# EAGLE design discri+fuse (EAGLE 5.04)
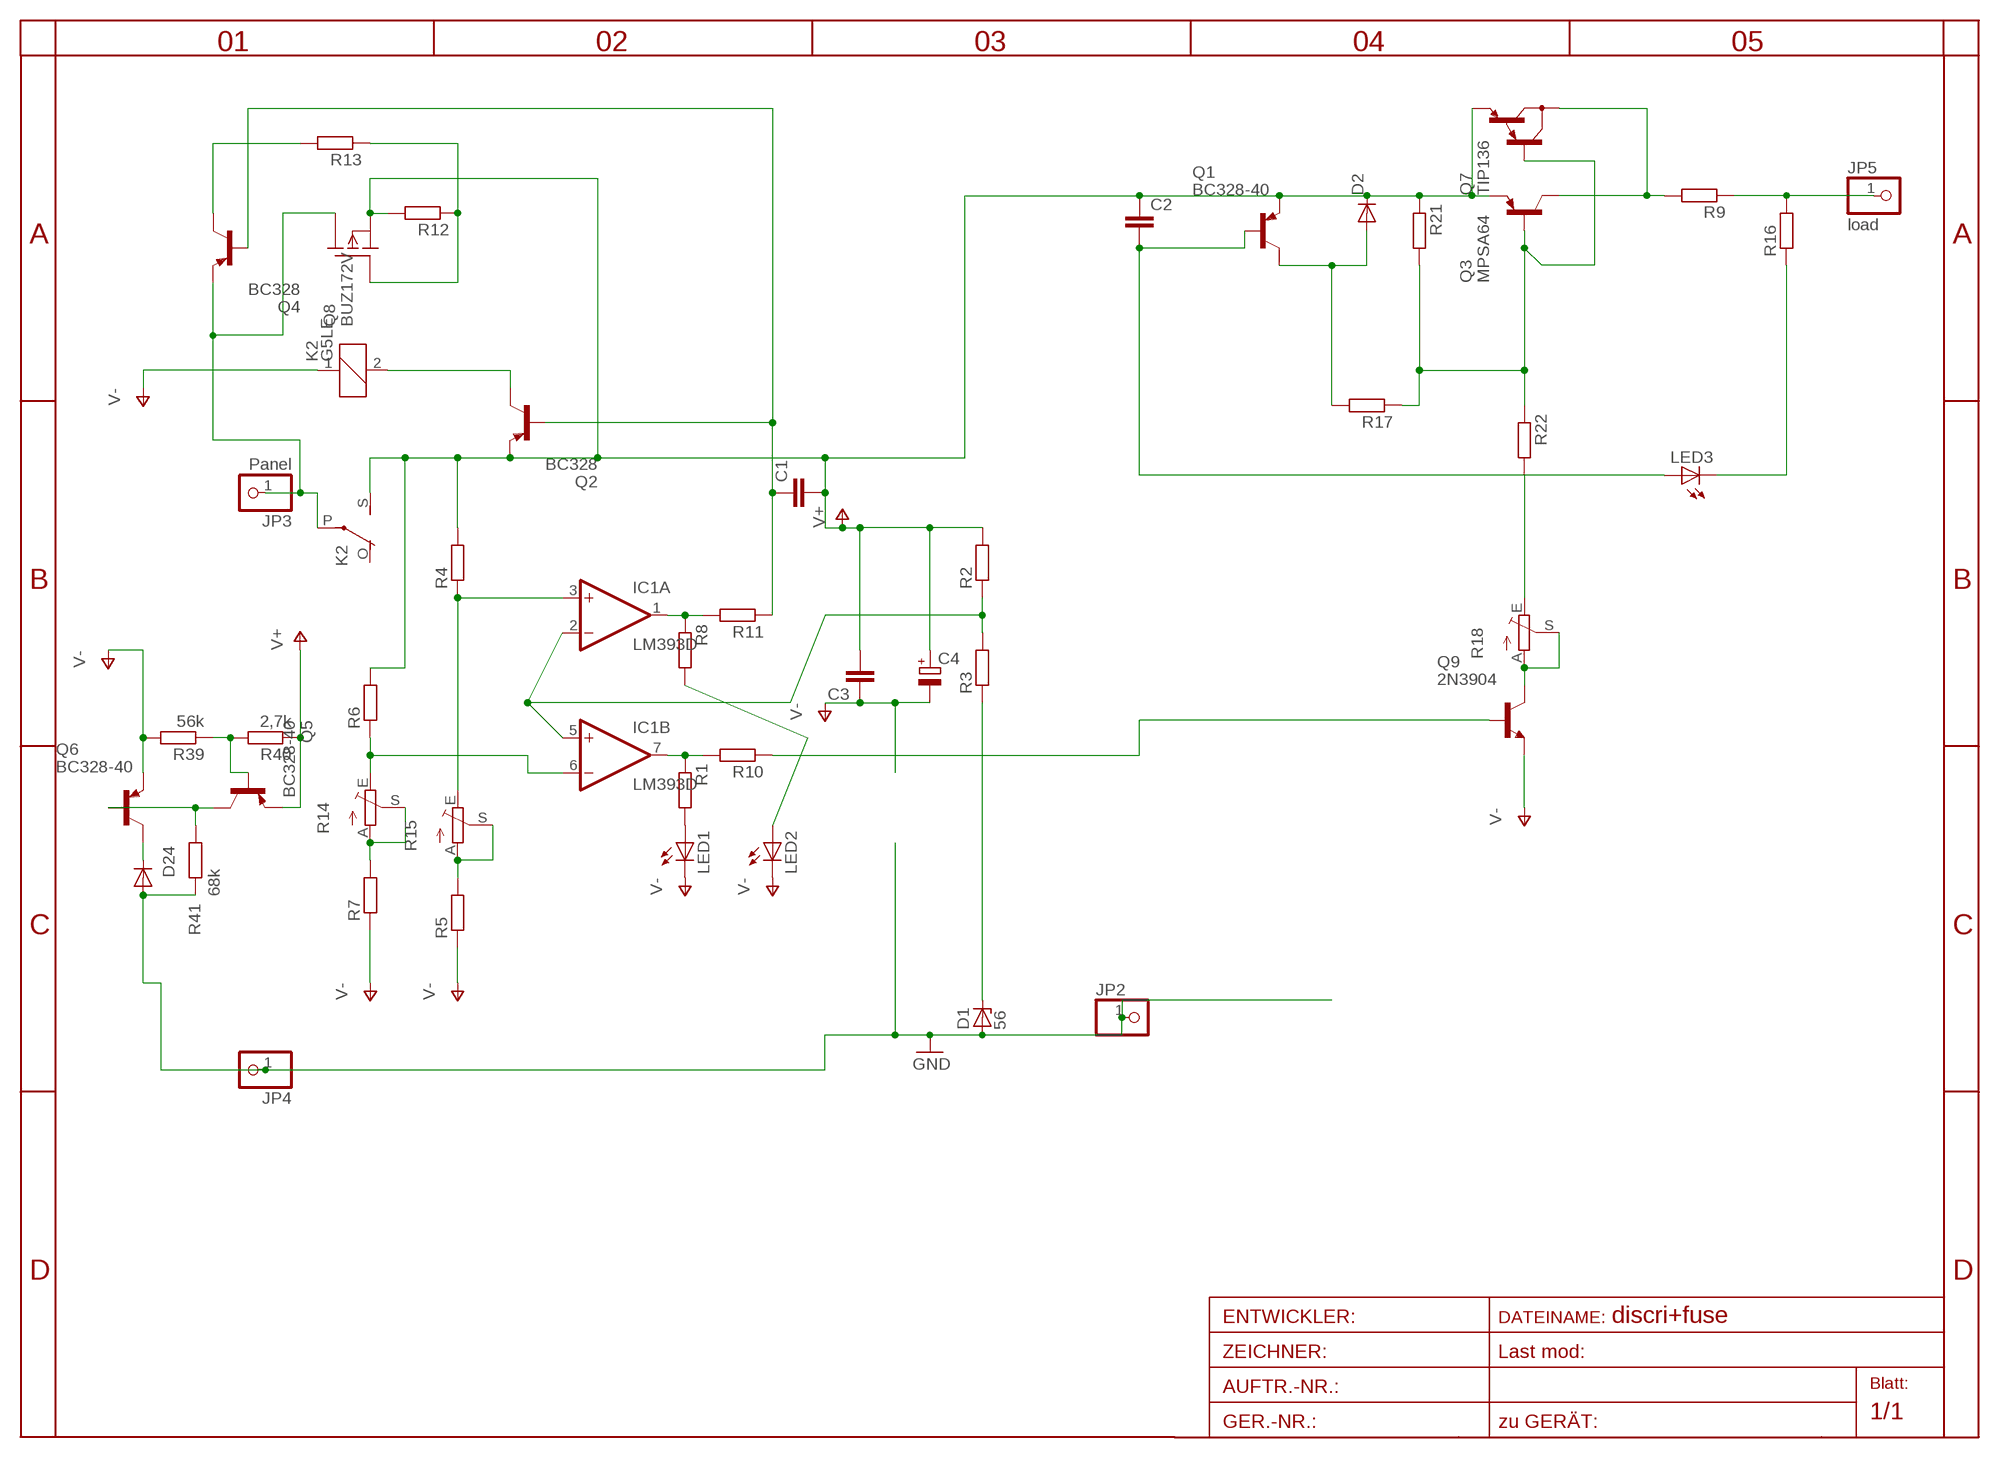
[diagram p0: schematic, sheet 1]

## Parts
C1  C-EU025-025X050  [C025-025X050]
C2  C-EU025-024X044  [C025-024X044]
C3  C-EU025-025X050  [C025-025X050]
C4  CPOL-EU5-13  [2,5-5-FLAT]
D1  56  ZENER-DIODEDO35Z10  [DO35Z10]
D2  DIODE-D-5  [D-5]
D24  Z20  DIODE-D-7.5  [D-7.5]
IC1  LM393D  [SO08]
JP2  PINHD-1X1  [1X01]
JP3  Panel  PINHD-1X1  [1X01]
JP4  PINHD-1X1  [1X01]
JP5  load  PINHD-1X1  [1X01]
K2  G5LE  [G5LE]
LED1  LED3MM  [LED3MM]
LED2  LED3MM  [LED3MM]
LED3  LED3MM  [LED3MM]
Q1  BC328-40  [TO92-EBC]
Q2  BC328  [TO92-EBC]
Q3  MPSA64  [TO92-CBE]
Q4  BC328  [TO92-EBC]
Q5  BC328-40  [TO92-EBC]
Q6  BC328-40  [TO92-EBC]
Q7  TIP136  [TO220]
Q8  BUZ172V  [TO220V]
Q9  2N3904  [TO92]
R1  R-EU_0207/15  [0207/15]
R2  R-EU_0204/7  [0204/7]
R3  R-EU_0204/7  [0204/7]
R4  R-EU_0204/7  [0204/7]
R5  R-EU_0204/7  [0204/7]
R6  R-EU_0204/7  [0204/7]
R7  R-EU_0204/7  [0204/7]
R8  R-EU_0207/20  [0207/20]
R9  R-EU_0204/5  [0204/5]
R10  R-EU_0207/15  [0207/15]
R11  R-EU_0204/7  [0204/7]
R12  R-EU_0204/7  [0204/7]
R13  R-EU_0204/7  [0204/7]
R14  TRIM_EU-CA6V  [CA6V]
R15  TRIM_EU-CA6V  [CA6V]
R16  R-EU_0207/12  [0207/12]
R17  R-EU_0204/5  [0204/5]
R18  TRIM_EU-CA6V  [CA6V]
R21  R-EU_0204/7  [0204/7]
R22  R-EU_0204/7  [0204/7]
R39  56k  R-EU_0204/7  [0204/7]
R40  2,7k  R-EU_0204/2V  [0204V]
R41  68k  R-EU_0207/10  [0207/10]

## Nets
GND: D1.A D24.A JP2.1 JP4.1 R41.2
N$1: D1.C R3.1
N$2: IC1.6(B:-IN) R6.1 R14.E
N$3: R7.2 R14.A R14.S
N$4: IC1.2(A:-IN) IC1.5(B:+IN) R2.1 R3.2
N$6: LED1.A R1.2
N$7: LED2.A R8.2
N$8: K2.2 Q2.C
N$9: D2.A Q1.C R17.2
N$10: Q3.B Q7.1(B) R17.1 R21.2 R22.1
N$11: R5.2 R15.A R15.S
N$12: IC1.3(A:+IN) R4.1 R15.E
N$13: D24.C Q6.C
N$14: IC1.1(A:OUT) R8.1 R11.2
N$15: IC1.7(B:OUT) R1.1 R10.2
N$16: C1.1 Q2.B Q4.B R11.1
N$17: JP5.1 R9.1 R16.2
N$18: LED3.K(C) R16.1
N$19: Q8.1(G) R12.1 R13.1
N$20: Q4.C R13.2
N$21: C2.2 LED3.A Q1.B
N$22: Q3.C Q7.2(C) R9.2
N$23: Q9.1(C) R18.A R18.S
N$24: R18.E R22.2
N$25: Q9.2(B) R10.1
N$38: Q5.C Q6.B R41.1
N$41: Q5.B R39.1 R40.2
PANEL: JP3.1 K2.P(2:P) Q4.E Q8.2(D)
V+: C1.2 C2.1 C3.2 C4.+ D2.C K2.S(2:S) Q1.E Q2.E Q3.E Q5.E Q7.3(E) Q8.3(S) R2.2 R4.2 R6.2 R12.2 R21.1 R40.1
V-: C3.1 C4.- K2.1 LED1.K(C) LED2.K(C) Q6.E Q9.3(E) R5.1 R7.1 R39.2
Unconnected: K2.O(2:O)

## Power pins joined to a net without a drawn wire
V+: IC1.8(P:V+)
V-: IC1.4(P:V-)

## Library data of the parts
C1-C3 = rcl-2:C-EU: CAPACITOR, European symbol
C4 = rcl-2:CPOL-EU: POLARIZED CAPACITOR, European symbol
D1 = diode-1:ZENER-DIODE: Z-Diode
D2 D24 = diode-1:DIODE-: DIODE
IC1 = linear:LM393: COMPARATOR
JP2-JP5 = pinhead:PINHD-1X1: PIN HEADER
K2 = relay2:G5LE: RELAY 1 x switch, 10 A/120 V AC, 8 A/30 V DC, Omron
LED1-LED3 = led:LED: LED
Q1 Q2 Q4-Q6 = transistor-pnp:BC328*: PNP Transistror
Q3 = transistor-pnp:MPSA64*: PNP Transistror
Q7 = transistor-pnp:TIP136: PNP Darlington Transistor
Q8 = transistor-fet:BUZ172: P-Channel Enhancement MOSFET -100V; -5A; 0,8Ohm
Q9 = transistor-npn:2N3904: NPN Transistor
R1-R13 R16 R17 R21 R22 R39-R41 = rcl-2:R-EU_: RESISTOR, European symbol
R14 R15 R18 = pot:TRIM_EU-: POTENTIOMETER

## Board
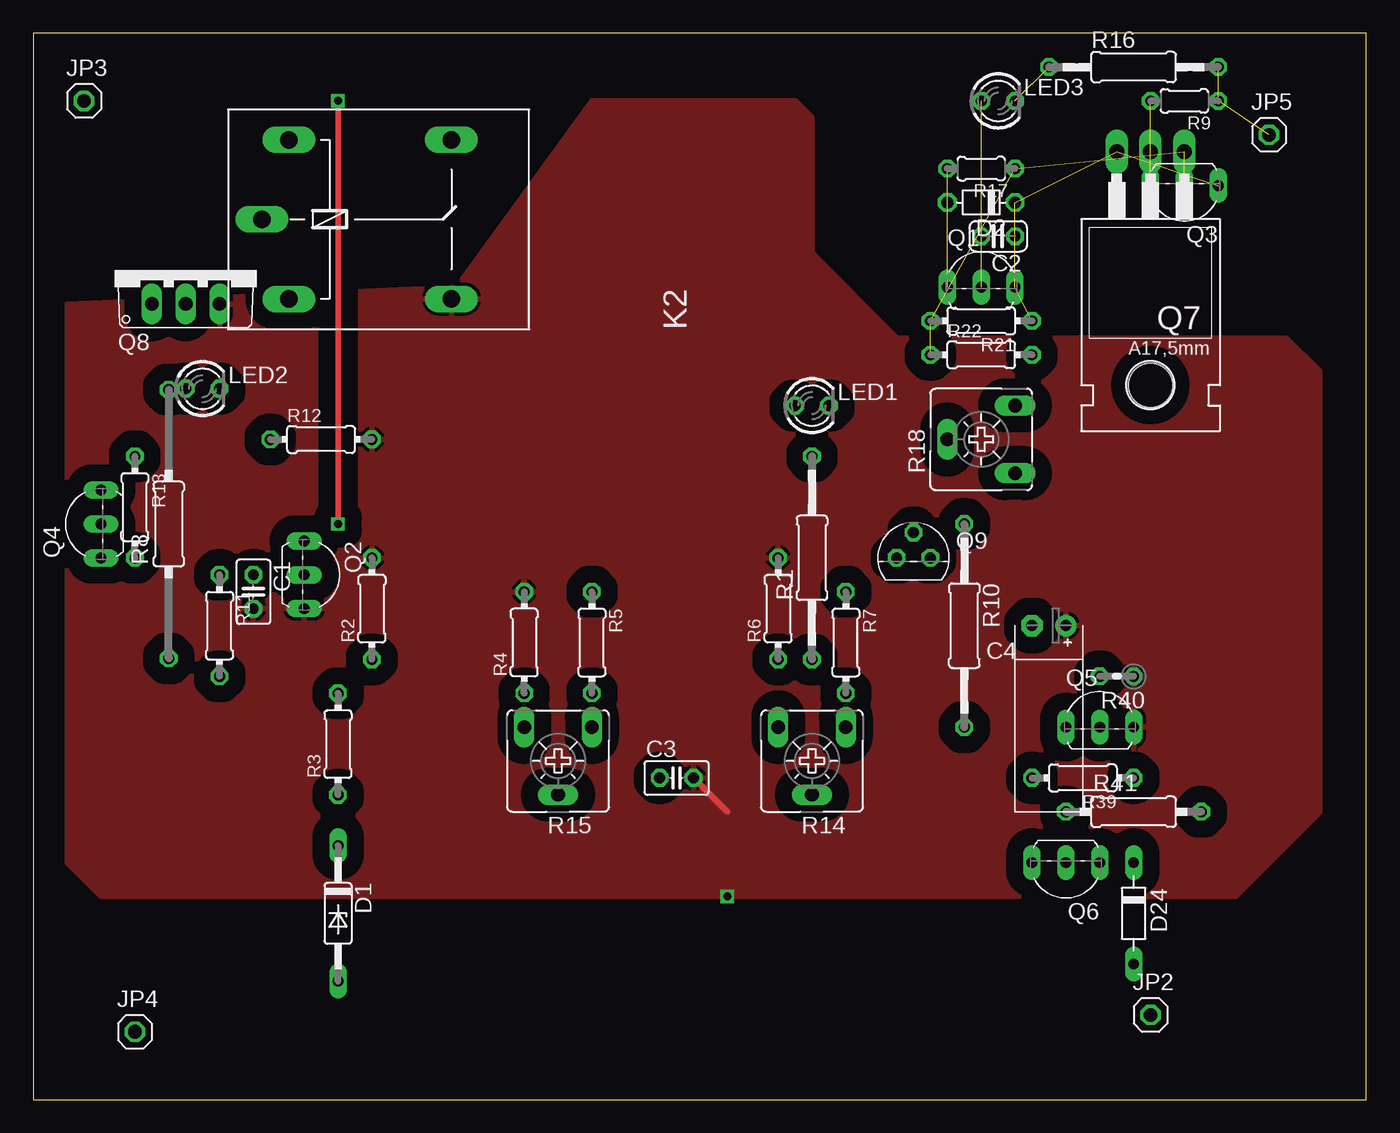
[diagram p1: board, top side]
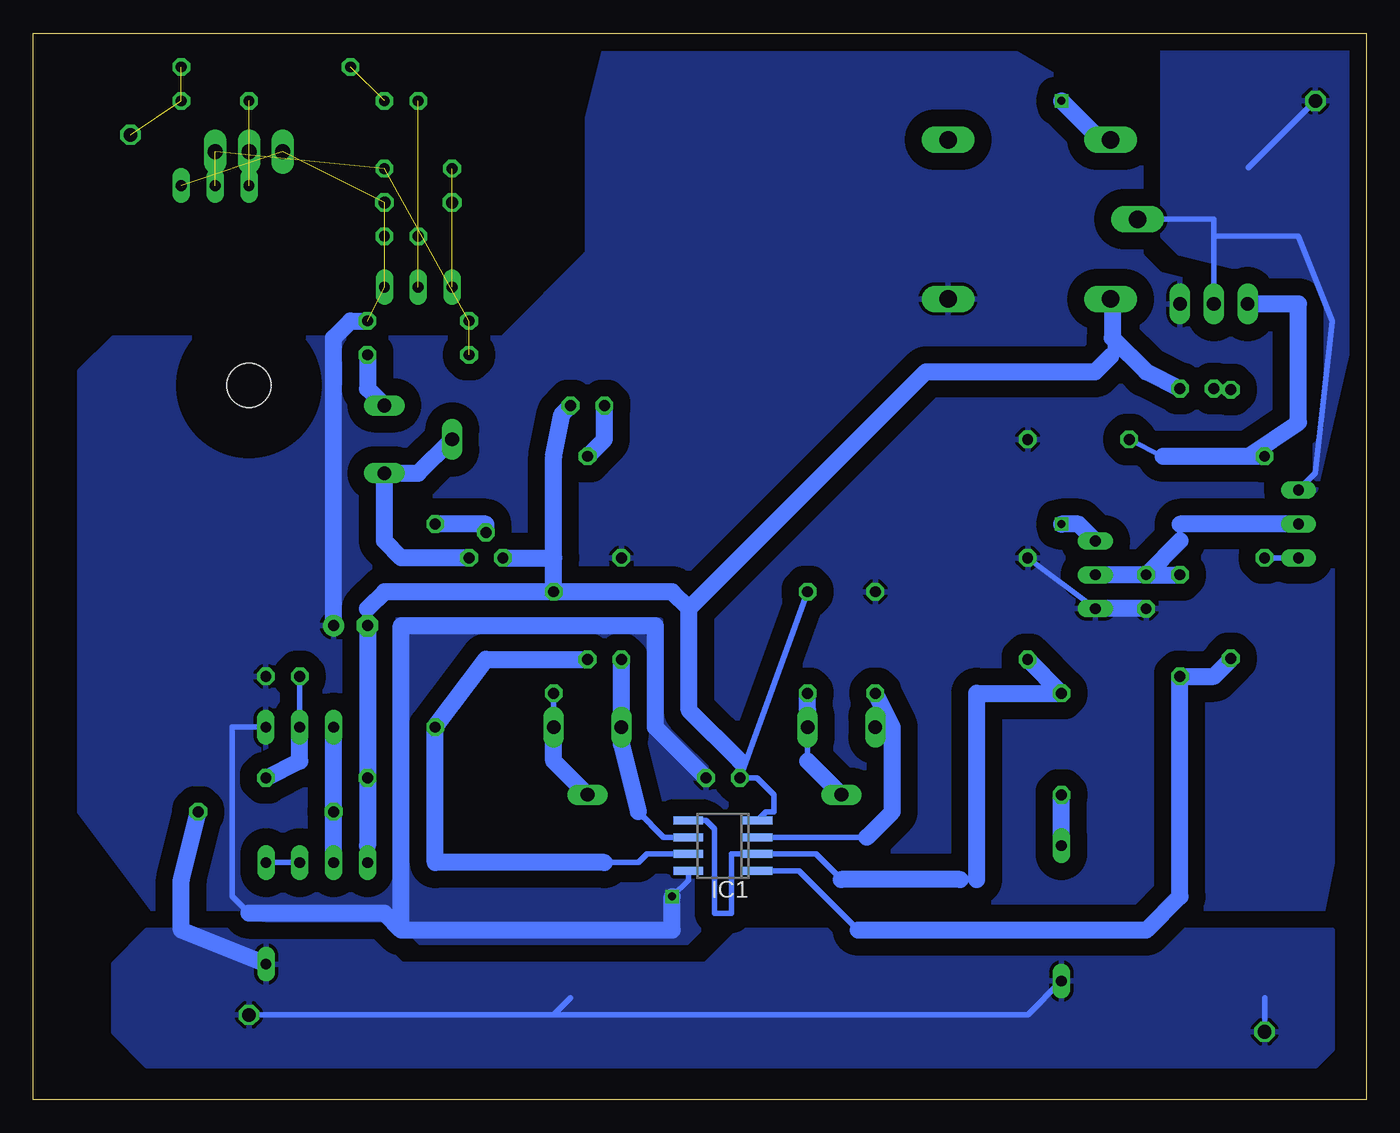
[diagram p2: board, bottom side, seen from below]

Size 100 x 80 mm. Coordinates in mm from the lower left corner, seen from the top.
Outline: 0,0 100,0 100,80 0,80 0,0
Copper layers (1*16): Top 0.035mm / dielectric 1.5mm / Bottom 0.035mm
Design rules "default": minimum track width 10mil, minimum drill 24mil, track to track 8mil, track to pad 8mil, pad to pad 8mil, via to via 8mil, smd to smd 8mil, copper to edge 40mil, drill to drill 8mil, minimum pad ring 10mil, minimum via ring 8mil, stop-mask expansion 4mil, vias tented up to drill 0mil, thermal gap 10mil

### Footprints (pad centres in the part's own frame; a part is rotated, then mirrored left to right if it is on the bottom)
C025-025X050 = drill 0.813 octagon: 1 -1.27,0; 2 1.27,0
C025-024X044 = drill 0.813 octagon: 1 -1.27,0; 2 1.27,0
2,5-5-FLAT = drill 0.813 pad 1.6 round: + -1.27,0 | drill 0.813 pad 1.6 octagon: - 1.27,0
DO35Z10 = drill 0.813 long: A 5.08,0; C -5.08,0
D-5 = drill 0.9 octagon: A 2.54,0; C -2.54,0
D-7.5 = drill 0.813 long: A 3.81,0; C -3.81,0
SO08 = smd 0.6 x 2.2: 1 -1.905,-2.6; 2 -0.635,-2.6; 3 0.635,-2.6; 4 1.905,-2.6; 5 1.905,2.6; 6 0.635,2.6; 7 -0.635,2.6; 8 -1.905,2.6
1X01 = drill 1.016 octagon: 1 0,0
G5LE = drill 1.321 long: 1 -7.493,-5.969; 2 -7.493,5.969; O 4.699,5.969; P -9.525,0; S 4.699,-5.969
LED3MM = drill 0.813 octagon: A -1.27,0; K 1.27,0
TO92-EBC = drill 0.813 long: B 0,-1.27; C -2.54,-1.27; E 2.54,-1.27
TO92-CBE = drill 0.813 long: B 0,0; C 2.54,0; E -2.54,0
TO220 = drill 1.118 long: 1 -2.54,-6.35; 2 0,-6.35; 3 2.54,-6.35 | hole 3.302: 0,11.176
TO220V = drill 1.016 long: 1 -2.54,-2.54; 2 0,-2.54; 3 2.54,-2.54
TO92 = drill 0.813 octagon: 1 1.27,0; 2 0,1.905; 3 -1.27,0
0207/15 = drill 0.813 octagon: 1 -7.62,0; 2 7.62,0
0204/7 = drill 0.813 octagon: 1 -3.81,0; 2 3.81,0
0207/20 = drill 0.813 octagon: 1 -10.08,0; 2 10.08,0
0204/5 = drill 0.813 octagon: 1 -2.54,0; 2 2.54,0
CA6V = drill 1.016 long: A -2.54,-2.54; E 2.54,-2.54; S 0,2.54
0207/12 = drill 0.813 octagon: 1 -6.35,0; 2 6.35,0
0204V = drill 0.813 octagon: 1 -1.27,0; 2 1.27,0
0207/10 = drill 0.813 octagon: 1 -5.08,0; 2 5.08,0

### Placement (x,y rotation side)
C1  16.51,38.1 270 top
C2  72.39,64.77 180 top
C3  48.26,24.13 0 top
C4  76.2,35.56 180 top
D1  22.86,13.97 270 top
D2  71.12,67.31 180 top
D24  82.55,13.97 270 top
IC1  48.26,19.05 90 bottom
JP2  83.82,6.35 0 top
JP3  3.81,74.93 0 top
JP4  7.62,5.08 0 top
JP5  92.71,72.39 0 top
K2  26.67,66.04 0 top
LED1  58.42,52.07 0 top
LED2  12.7,53.34 0 top
LED3  72.39,74.93 0 top
Q1  71.12,62.23 0 top
Q2  21.59,39.37 270 top
Q3  86.36,68.58 180 top
Q4  3.81,43.18 90 top
Q5  80.01,29.21 0 top
Q6  77.47,16.51 180 top
Q7  83.82,64.77 180 top
Q8  11.43,62.23 0 top
Q9  66.04,40.64 0 top
R1  58.42,40.64 90 top
R2  25.4,36.83 90 top
R3  22.86,26.67 90 top
R4  36.83,34.29 90 top
R5  41.91,34.29 270 top
R6  55.88,36.83 90 top
R7  60.96,34.29 270 top
R8  10.16,43.18 90 top
R9  86.36,74.93 180 top
R10  69.85,35.56 270 top
R11  13.97,35.56 270 top
R12  21.59,49.53 0 top
R13  7.62,44.45 270 top
R14  58.42,25.4 180 top
R15  39.37,25.4 180 top
R16  82.55,77.47 0 top
R17  71.12,69.85 180 top
R18  71.12,49.53 90 top
R21  71.12,58.42 180 top
R22  71.12,55.88 0 top
R39  78.74,24.13 180 top
R40  81.28,31.75 180 top
R41  82.55,21.59 0 top

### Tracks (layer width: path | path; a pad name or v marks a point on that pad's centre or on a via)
GND
  Bottom 0.406: 62.23,6.35 60.96,6.35 59.69,7.62 | 62.23,6.35 JP2.1 | D1.A 25.4,6.35 62.23,6.35 | JP4.1 7.62,7.62
  Bottom 1.27: D24.A 88.9,12.7 88.9,16.51 R41.2
  pour Bottom (isolate 1.27, rank 4): 2.54,12.7 46.99,12.7 49.53,10.16 72.39,10.16 74.93,12.7 91.44,12.7 93.98,10.16 93.98,5.08 91.44,2.54 3.81,2.54 2.54,3.81
N$1
  Bottom 1.27: D1.C R3.1
N$2
  Bottom 0.406: IC1.6 52.7,19.68 54.61,21.59 | 55.88,26.67 R14.E
  Bottom 1.27: R14.E R6.1 | 54.61,21.59 55.88,26.67
N$3
  Bottom 0.406: R14.A R7.2
  Bottom 1.27: R14.S 60.96,25.4 R14.A
N$4
  Bottom 0.406: 39.37,16.51 41.27,18.41 IC1.2 47.62,18.41 47.62,13.97 48.9,13.97 48.9,20.32 49.53,20.95 IC1.5 | 29.21,16.51 30.48,16.51
  Bottom 1.27: 30.48,16.51 39.37,16.51 | 29.21,16.51 29.21,30.48 R3.2 R2.1
N$6
  Bottom 1.27: R1.2 57.15,49.53 LED1.A
N$7
  Bottom 0.406: R8.2 LED2.A
N$8  (via drill 0.6)
  Top 0.406: v22.86,43.18 v22.86,74.93
  Bottom 0.406: 19.94,72.01 K2.2
  Bottom 1.27: v22.86,74.93 19.94,72.01 | v22.86,43.18 21.59,43.18 Q2.C
N$9  (2 unrouted)
N$10  (4 unrouted)
N$11
  Bottom 0.406: 41.91,25.4 R15.A 41.91,29.21
  Bottom 1.27: R15.S 41.91,25.4 | 41.91,29.21 R5.2
N$12
  Bottom 0.406: 37.47,19.68 IC1.3
  Bottom 1.27: 35.56,27.94 35.56,21.59 37.47,19.68 | 35.56,27.94 R4.1 | 35.56,27.94 R15.E
N$13
  Bottom 0.406: Q6.C D24.C
N$14
  Bottom 0.406: IC1.1 42.55,17.14 38.1,12.7 | 10.16,33.02 R8.1
  Bottom 1.27: 38.1,12.7 16.51,12.7 13.97,15.24 R11.2 11.43,31.75 10.16,33.02
N$15
  Bottom 0.406: IC1.7 53.98,18.41 54.61,17.78 57.15,17.78
  Bottom 1.27: 57.15,17.78 69.85,17.78 R10.2 66.04,33.02 R1.1
N$16
  Bottom 0.406: 13.97,43.18 13.97,41.91
  Bottom 1.27: Q4.B 13.97,43.18 | 13.97,41.91 C1.1 | C1.1 R11.1 | C1.1 Q2.B
N$17  (2 unrouted)
N$18  (1 unrouted)
N$19
  Bottom 0.406: 8.89,48.26 15.24,48.26 R12.1
  Bottom 1.27: 8.89,48.26 5.08,50.8 5.08,59.69 Q8.1 | R13.1 15.24,48.26
N$20
  Bottom 0.406: Q4.C R13.2
N$21  (2 unrouted)
N$22  (2 unrouted)
N$23
  Bottom 1.27: Q9.1 72.39,40.64 73.66,41.91 R18.A 71.12,46.99 R18.S
N$24
  Bottom 1.27: R22.2 74.93,53.34 R18.E
N$25
  Bottom 1.27: Q9.2 66.04,43.18 R10.1
N$38
  Bottom 1.27: Q6.B R41.1 Q5.C
N$41
  Bottom 0.406: Q5.B R40.2
  Bottom 1.27: R39.1 80.01,25.4 Q5.B
PANEL
  Bottom 0.406: JP3.1 8.83,69.91 | Q4.E 3.81,46.99 2.54,58.42 5.08,64.77 11.43,64.77 | Q8.2 11.43,66.04 K2.P
  pour Bottom (isolate 1.27): 0,80.01 0,62.23 3.81,45.72 3.81,60.96 13.97,63.5 15.24,64.77 15.24,80.01
V+  (via drill 0.6)  (5 unrouted)
  Top 0.406: C3.2 52.07,21.59
  Bottom 0.406: Q2.E R2.2 | IC1.8 50.86,16.45 v52.07,15.24 | 83.82,13.97 85.09,15.24 85.09,27.94 Q5.E
  Bottom 1.27: C1.2 Q2.E | v52.07,15.24 52.07,12.7 72.39,12.7 | 83.82,13.97 73.66,13.97 72.39,12.7 | 72.39,12.7 72.39,35.56 53.34,35.56 53.34,27.94 C3.2 | R21.1 76.2,58.42 77.47,57.15 C4.+
  pour Bottom (isolate 1.27, rank 5): 26.67,78.74 57.15,78.74 58.42,73.66 58.42,63.5 64.77,57.15 93.98,57.15 96.52,54.61 96.52,21.59 88.9,11.43 3.81,11.43 2.54,17.78 2.54,63.5 5.08,66.04
  pour Top (isolate 1.27, rank 5): 41.91,74.93 57.15,74.93 58.42,73.66 58.42,63.5 64.77,57.15 93.98,57.15 96.52,54.61 96.52,21.59 90.17,15.24 5.08,15.24 2.54,17.78 2.54,59.69 31.75,60.96
V-
  Bottom 0.406: C3.1 45.72,24.13 44.45,22.86 44.45,21.59 45.02,21.59 IC1.4 | C3.1 R5.1 | C3.1 46.99,25.4 | 74.93,36.83 C4.- | 74.93,19.05 Q6.E | 19.05,59.94 K2.1 19.18,55.75
  Bottom 1.27: 46.99,25.4 50.8,29.21 50.8,36.83 | 50.8,36.83 52.07,38.1 R7.1 | R7.1 73.66,38.1 74.93,36.83 | C4.- R39.2 74.93,19.05 | LED2.K 16.51,54.61 19.05,57.15 19.05,59.94 | 19.18,55.75 20.32,54.61 33.02,54.61 50.8,36.83 | R7.1 60.96,40.64 | 60.96,40.64 60.96,48.26 60.33,51.44 LED1.K | Q9.3 60.96,40.64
